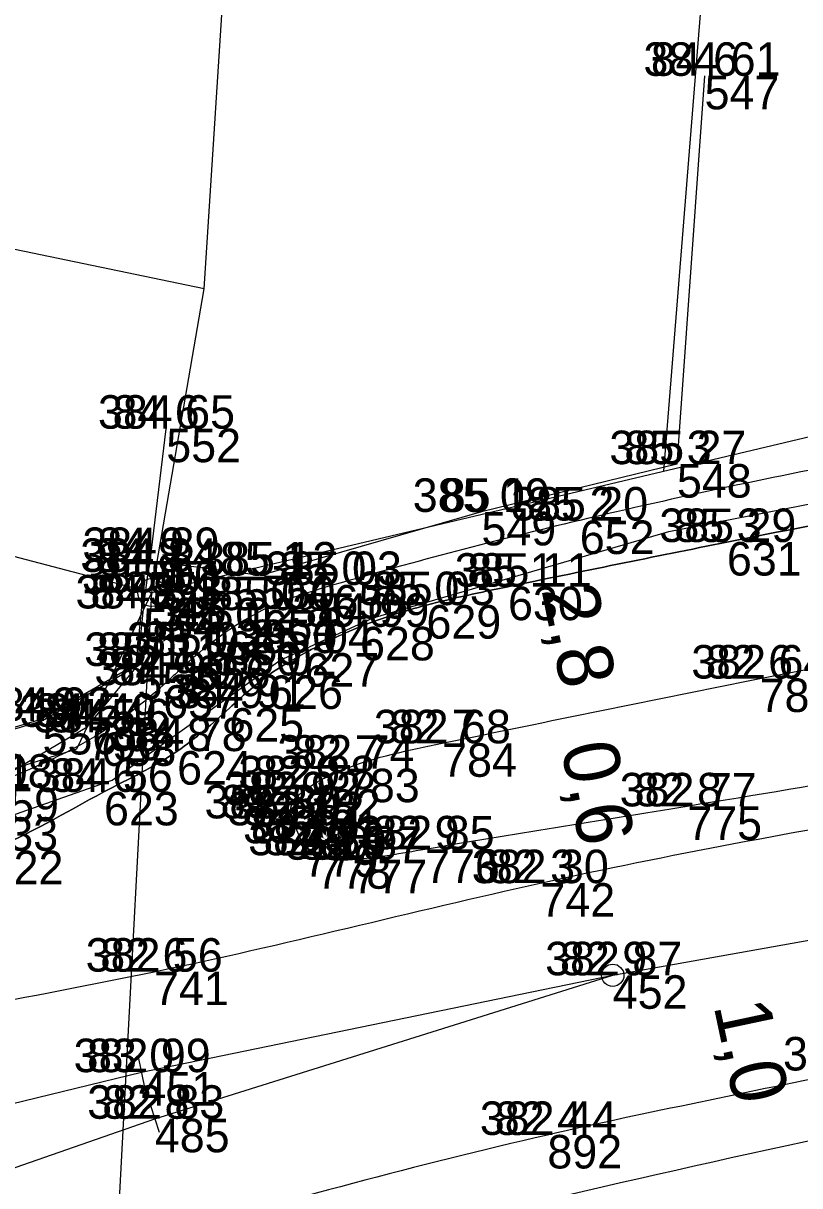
# Model space of a CAD drawing. Extents: x -514509 to -512782, y -1144610 to -1143439.
# Drawn here: x -513252.99 to -513225.18, y -1143600.5 to -1143558.86 of the extents above; entities that cross this region are included whole.
import ezdxf

# ---------------------------------------------------------------- set-up
doc = ezdxf.new("R2010")
doc.units = 0
for name, color, linetype in [('Vrstva 1', 7, 'Continuous'), ('Vrstva 10', 7, 'Continuous'), ('Vrstva 11', 7, 'Continuous'), ('Vrstva 12', 7, 'Continuous'), ('Vrstva 46', 7, 'Continuous'), ('Vrstva 48', 7, 'Continuous'), ('Vrstva 57', 7, 'Continuous'), ('Vrstva 58', 7, 'Continuous'), ('Vrstva 59', 7, 'Continuous'), ('Vrstva 6', 7, 'Continuous'), ('Vrstva 60', 7, 'Continuous'), ('Vrstva 8', 7, 'Continuous')]:
    doc.layers.add(name, color=color, linetype=linetype)

msp = doc.modelspace()

# ---------------------------------------------------------------- linework, layer by layer
at = {"layer": 'Vrstva 1'}
msp.add_lwpolyline([(-513255.856, -1143588.1), (-513249.812, -1143585.976), (-513243.787, -1143581.668), (-513240.465, -1143580.159), (-513229.874, -1143577.066), (-513220.491, -1143575.228), (-513193.623, -1143570.982)], dxfattribs=at)
at = {"layer": 'Vrstva 10'}
for p, q in [((-513250.415, -1143617.382), (-513248.39, -1143579.25)), ((-513248.442, -1143579.251), (-513248.342, -1143579.251)), ((-513248.442, -1143579.251), (-513248.342, -1143579.251)), ((-513248.442, -1143579.251), (-513248.342, -1143579.251)), ((-513248.442, -1143579.251), (-513248.342, -1143579.251)), ((-513248.401, -1143579.299), (-513248.379, -1143579.201)), ((-513248.401, -1143579.299), (-513248.379, -1143579.201)), ((-513248.401, -1143579.299), (-513248.379, -1143579.201))]:
    msp.add_line(p, q, dxfattribs=at)
for points in [[(-513582.696, -1143761.24), (-513581.966, -1143752.218), (-513543.007, -1143722.265), (-513536.98, -1143726.125), (-513503.11, -1143701.59), (-513467.163, -1143704.368), (-513409.406, -1143670.068), (-513367.763, -1143641.182), (-513337.875, -1143622.14), (-513302.677, -1143606.244), (-513297.569, -1143595.846), (-513289.461, -1143596.696), (-513287.694, -1143584.666), (-513262.147, -1143588.316), (-513251.067, -1143584.844), (-513248.39, -1143579.25), (-513218.784, -1143572.229), (-513191.434, -1143567.629), (-513154.1, -1143564.42), (-513082.649, -1143574.448)], [(-513582.696, -1143761.24), (-513581.966, -1143752.218), (-513543.007, -1143722.265), (-513536.98, -1143726.125), (-513503.11, -1143701.59), (-513467.163, -1143704.368), (-513409.406, -1143670.068), (-513367.763, -1143641.182), (-513337.875, -1143622.14), (-513302.677, -1143606.244), (-513297.569, -1143595.846), (-513289.461, -1143596.696), (-513287.694, -1143584.666), (-513262.147, -1143588.316), (-513251.067, -1143584.844), (-513248.39, -1143579.25), (-513218.784, -1143572.229), (-513191.434, -1143567.629), (-513154.1, -1143564.42), (-513082.649, -1143574.448)], [(-513248.898, -1143581.879), (-513252.304, -1143583.85), (-513256.484, -1143585.088), (-513261.272, -1143585.929), (-513266.919, -1143586.377), (-513271.818, -1143586.191), (-513275.455, -1143587.207), (-513272.851, -1143588.177), (-513269.418, -1143588.55)], [(-513254.387, -1143586.238), (-513250.697, -1143584.065), (-513248.898, -1143581.879)]]:
    msp.add_lwpolyline(points, dxfattribs=at)
for centre in [(-513248.392, -1143579.251), (-513248.392, -1143579.251), (-513248.392, -1143579.251), (-513248.392, -1143579.251), (-513248.39, -1143579.25), (-513248.39, -1143579.25), (-513248.39, -1143579.25)]:
    msp.add_circle(centre, 0.499, dxfattribs=at)
for points in [[(-513123.946, -1143569.095), (-513136.959, -1143567.384), (-513147.544, -1143566.738), (-513160.182, -1143566.568), (-513173.688, -1143567.587), (-513189.822, -1143569.464), (-513207.783, -1143571.88), (-513222.493, -1143574.402), (-513233.063, -1143576.666), (-513241.875, -1143578.979), (-513244.418, -1143579.885), (-513245.683, -1143580.636), (-513246.818, -1143581.512), (-513247.979, -1143582.57), (-513250.194, -1143584.261), (-513254.387, -1143586.238), (-513258.899, -1143587.657), (-513263.404, -1143588.363), (-513269.418, -1143588.55), (-513272.851, -1143588.177)], [(-513257.245, -1143589.431), (-513254.229, -1143588.505), (-513250.102, -1143586.392), (-513247.476, -1143584.933), (-513245.605, -1143583.389), (-513244.222, -1143582.217), (-513242.919, -1143581.425), (-513240.929, -1143580.476), (-513238.55, -1143579.701), (-513235.633, -1143579.04), (-513227.79, -1143577.445), (-513216.392, -1143575.319), (-513202.945, -1143573.374), (-513183.589, -1143570.866), (-513165.858, -1143569.141), (-513150.059, -1143568.836), (-513140.147, -1143569.606), (-513128.565, -1143571.075), (-513110.146, -1143573.354)], [(-513110.146, -1143573.354), (-513128.565, -1143571.075), (-513140.147, -1143569.606), (-513150.059, -1143568.836), (-513165.858, -1143569.141), (-513183.589, -1143570.866), (-513202.945, -1143573.374), (-513216.392, -1143575.319), (-513227.79, -1143577.445), (-513235.633, -1143579.04), (-513238.55, -1143579.701), (-513240.929, -1143580.476), (-513242.919, -1143581.425), (-513244.222, -1143582.217), (-513245.605, -1143583.389), (-513247.476, -1143584.933), (-513250.102, -1143586.392), (-513254.229, -1143588.505), (-513257.245, -1143589.431)], [(-513214.733, -1143584.448), (-513229.213, -1143586.91), (-513238.6, -1143588.453), (-513241.201, -1143588.819), (-513242.494, -1143588.658), (-513242.951, -1143588.231), (-513243.264, -1143587.589), (-513243.39, -1143586.875), (-513242.873, -1143586.302), (-513241.47, -1143585.565), (-513237.994, -1143584.65), (-513226.616, -1143582.332), (-513214.669, -1143580.21), (-513199.307, -1143578.201), (-513184.01, -1143576.618), (-513174.841, -1143576.254), (-513159.12, -1143575.498), (-513141.488, -1143576.138)], [(-513276.152, -1143596.997), (-513274.802, -1143597.59), (-513272.927, -1143598.05), (-513268.755, -1143597.873), (-513261.681, -1143595.809), (-513248.307, -1143592.834), (-513234.475, -1143589.658), (-513220.565, -1143587), (-513211.071, -1143585.455)], [(-513105.656, -1143589.572), (-513111.398, -1143588.825), (-513120.896, -1143588.124), (-513127.781, -1143587.815), (-513134.493, -1143587.399), (-513145.289, -1143587.917), (-513154.263, -1143588.165), (-513167.107, -1143589.025), (-513183.18, -1143590.33), (-513202.182, -1143592.368), (-513213.364, -1143594.183), (-513223.359, -1143596.374), (-513234.22, -1143598.682), (-513248.131, -1143602.316), (-513262.889, -1143606.569), (-513272.412, -1143609.783), (-513278.746, -1143612.526), (-513284.257, -1143615.463), (-513287.251, -1143617.25), (-513289.125, -1143618.716), (-513289.862, -1143619.586), (-513289.805, -1143620.367), (-513289.601, -1143620.971)], [(-513125.264, -1143589.045), (-513135.661, -1143588.368), (-513143.283, -1143588.407), (-513146.019, -1143588.597), (-513154.875, -1143589.536), (-513169.823, -1143590.946), (-513182.203, -1143592.15), (-513200.496, -1143594.572), (-513221.669, -1143598.242), (-513242.802, -1143603.101), (-513261.502, -1143608.166), (-513271.576, -1143611.724), (-513278.023, -1143614.872), (-513282.94, -1143617.541)]]:
    msp.add_spline(points, degree=3, dxfattribs=at)
at = {"layer": 'Vrstva 12'}
for points in [[(-513228.589, -1143560.737), (-513229.58, -1143574.652), (-513236.576, -1143576.364), (-513244.492, -1143578.643), (-513248.449, -1143578.123), (-513247.868, -1143573.38)], [(-513228.589, -1143560.737), (-513229.58, -1143574.652), (-513236.576, -1143576.364), (-513244.492, -1143578.643), (-513248.449, -1143578.123), (-513247.868, -1143573.38)], [(-513228.589, -1143560.737), (-513229.58, -1143574.652), (-513236.576, -1143576.364), (-513244.492, -1143578.643), (-513248.449, -1143578.123), (-513247.868, -1143573.38)], [(-513248.449, -1143578.123), (-513248.526, -1143578.514)], [(-513248.449, -1143578.123), (-513248.526, -1143578.514)], [(-513248.526, -1143578.514), (-513248.695, -1143579.822)], [(-513248.526, -1143578.514), (-513248.695, -1143579.822)], [(-513248.753, -1143579.775), (-513248.956, -1143581.832), (-513252.362, -1143583.803), (-513256.542, -1143585.041), (-513261.33, -1143585.882), (-513266.977, -1143586.33)], [(-513248.695, -1143579.822), (-513248.898, -1143581.879), (-513252.304, -1143583.85), (-513256.484, -1143585.088), (-513261.272, -1143585.929), (-513266.919, -1143586.377)], [(-513248.695, -1143579.822), (-513248.898, -1143581.879), (-513252.304, -1143583.85), (-513256.484, -1143585.088), (-513261.272, -1143585.929), (-513266.919, -1143586.377)]]:
    msp.add_lwpolyline(points, dxfattribs=at)
at = {"layer": 'Vrstva 46'}
for points in [[(-513228.589, -1143560.737), (-513229.58, -1143574.652), (-513236.576, -1143576.364), (-513244.492, -1143578.643), (-513248.449, -1143578.123), (-513247.868, -1143573.38)], [(-513248.449, -1143578.123), (-513248.526, -1143578.514)], [(-513248.526, -1143578.514), (-513248.695, -1143579.822)], [(-513248.695, -1143579.822), (-513248.898, -1143581.879), (-513252.304, -1143583.85), (-513256.484, -1143585.088), (-513261.272, -1143585.929), (-513266.919, -1143586.377)]]:
    msp.add_lwpolyline(points, dxfattribs=at)
at = {"layer": 'Vrstva 48'}
msp.add_line((-513248.442, -1143579.251), (-513248.342, -1143579.251), dxfattribs=at)
msp.add_circle((-513248.392, -1143579.251), 0.499, dxfattribs=at)
at = {"layer": 'Vrstva 6'}
for points in [[(-513413.969, -1143682.409), (-513403.805, -1143675.248), (-513392.133, -1143667.024), (-513380.381, -1143658.412), (-513367.637, -1143649.641), (-513357.691, -1143643.188), (-513346.467, -1143636.319), (-513334.512, -1143629.443), (-513322.183, -1143622.808), (-513313.555, -1143618.663), (-513300.91, -1143613.176), (-513292.314, -1143609.739), (-513280.019, -1143605.312), (-513267.676, -1143601.424), (-513256.27, -1143598.259), (-513248.762, -1143596.434), (-513231.877, -1143592.957), (-513218.03, -1143590.48), (-513208.28, -1143588.89)], [(-513473.254, -1143729.922), (-513459.481, -1143720.255), (-513446.15, -1143710.9), (-513437.145, -1143704.535), (-513426.35, -1143697.32), (-513415.342, -1143689.242), (-513413.529, -1143687.978), (-513401.76, -1143679.778), (-513389.139, -1143671.043), (-513376.721, -1143662.484), (-513364.496, -1143654.101), (-513352.892, -1143646.776), (-513340.089, -1143639.199), (-513329.801, -1143633.48), (-513318.088, -1143627.265), (-513306.168, -1143621.42), (-513292.483, -1143615.146), (-513278.194, -1143609.101), (-513263.261, -1143603.326), (-513248.282, -1143598.104), (-513231.877, -1143592.957)]]:
    msp.add_lwpolyline(points, dxfattribs=at)
at = {"layer": 'Vrstva 60'}
for p, q in [((-513228.59, -1143560.74), (-513228.59, -1143560.74)), ((-513247.87, -1143573.38), (-513247.87, -1143573.38)), ((-513229.58, -1143574.65), (-513229.58, -1143574.65)), ((-513236.58, -1143576.36), (-513236.58, -1143576.36)), ((-513233.06, -1143576.67), (-513233.06, -1143576.67)), ((-513227.79, -1143577.44), (-513227.79, -1143577.44)), ((-513248.45, -1143578.12), (-513248.45, -1143578.12)), ((-513248.53, -1143578.51), (-513248.53, -1143578.51)), ((-513244.49, -1143578.64), (-513244.49, -1143578.64)), ((-513241.88, -1143578.98), (-513241.88, -1143578.98)), ((-513235.63, -1143579.04), (-513235.63, -1143579.04)), ((-513248.39, -1143579.25), (-513248.39, -1143579.25)), ((-513248.7, -1143579.82), (-513248.7, -1143579.82)), ((-513244.42, -1143579.88), (-513244.42, -1143579.88)), ((-513238.55, -1143579.7), (-513238.55, -1143579.7)), ((-513245.68, -1143580.64), (-513245.68, -1143580.64)), ((-513240.93, -1143580.48), (-513240.93, -1143580.48)), ((-513246.82, -1143581.51), (-513246.82, -1143581.51)), ((-513242.92, -1143581.42), (-513242.92, -1143581.42)), ((-513248.9, -1143581.88), (-513248.9, -1143581.88)), ((-513244.22, -1143582.22), (-513244.22, -1143582.22)), ((-513226.62, -1143582.33), (-513226.62, -1143582.33)), ((-513247.98, -1143582.57), (-513247.98, -1143582.57)), ((-513245.61, -1143583.39), (-513245.61, -1143583.39)), ((-513252.3, -1143583.85), (-513252.3, -1143583.85)), ((-513250.7, -1143584.06), (-513250.7, -1143584.06)), ((-513250.19, -1143584.26), (-513250.19, -1143584.26)), ((-513237.99, -1143584.65), (-513237.99, -1143584.65)), ((-513247.48, -1143584.93), (-513247.48, -1143584.93)), ((-513241.47, -1143585.56), (-513241.47, -1143585.56)), ((-513250.1, -1143586.39), (-513250.1, -1143586.39)), ((-513242.87, -1143586.3), (-513242.87, -1143586.3)), ((-513243.39, -1143586.87), (-513243.39, -1143586.87)), ((-513229.21, -1143586.91), (-513229.21, -1143586.91)), ((-513244.04, -1143587.34), (-513244.04, -1143587.34)), ((-513243.26, -1143587.59), (-513243.26, -1143587.59)), ((-513242.95, -1143588.23), (-513242.95, -1143588.23)), ((-513238.6, -1143588.45), (-513238.6, -1143588.45)), ((-513242.49, -1143588.66), (-513242.49, -1143588.66)), ((-513241.2, -1143588.82), (-513241.2, -1143588.82)), ((-513234.47, -1143589.66), (-513234.47, -1143589.66)), ((-513248.31, -1143592.83), (-513248.31, -1143592.83)), ((-513231.88, -1143592.96), (-513231.88, -1143592.96)), ((-513248.76, -1143596.43), (-513248.76, -1143596.43)), ((-513248.28, -1143598.1), (-513248.28, -1143598.1)), ((-513234.22, -1143598.68), (-513234.22, -1143598.68))]:
    msp.add_line(p, q, dxfattribs=at)
at = {"layer": 'Vrstva 8'}
for p, q in [((-513225.43, -1143517.387), (-513230.062, -1143574.902)), ((-513248.863, -1143595.944), (-513248.66, -1143596.923)), ((-513248.434, -1143597.627), (-513248.129, -1143598.58))]:
    msp.add_line(p, q, dxfattribs=at)
for points in [[(-513248.39, -1143579.25), (-513246.509, -1143568.365), (-513245.688, -1143555.576), (-513244.124, -1143532.119), (-513243.762, -1143521.861), (-513243.25, -1143516.407), (-513242.174, -1143505.947), (-513250.332, -1143503.086), (-513258.171, -1143503.979), (-513270.878, -1143501.241)], [(-513246.509, -1143568.365), (-513266.87, -1143564.142), (-513267.555, -1143566.209), (-513265.928, -1143569.992), (-513266.625, -1143574.454)], [(-513285.741, -1143571.052), (-513277.74, -1143572.569), (-513275.312, -1143572.787), (-513272.999, -1143573.349), (-513266.625, -1143574.454), (-513248.39, -1143579.25)]]:
    msp.add_lwpolyline(points, dxfattribs=at)
msp.add_circle((-513231.88, -1143592.96), 0.4, dxfattribs=at)

# ---------------------------------------------------------------- texts
at = {"layer": 'Vrstva 11'}
for s, rotation, p in [('2,8', 281.5169, (-513234.438, -1143579.14)), ('0,6', 280.8194, (-513233.739, -1143584.77)), ('1,0', 281.9959, (-513228.272, -1143594.045))]:
    msp.add_text(s, height=2, rotation=rotation, dxfattribs=at).set_placement(p)
at = {"layer": 'Vrstva 57'}
for s, p in [('84 6 ', (-513230.514, -1143560.74)), ('84 6 ', (-513249.794, -1143573.38)), ('85 3 ', (-513231.463, -1143574.65)), ('85 1 ', (-513238.038, -1143576.36)), ('85 2 ', (-513234.943, -1143576.67)), ('85 3 ', (-513229.673, -1143577.44)), ('84 9 ', (-513250.338, -1143578.12)), ('84 8 ', (-513250.413, -1143578.51)), ('85 1 ', (-513245.948, -1143578.64)), ('85 0 ', (-513243.828, -1143578.98)), ('85 0 ', (-513250.338, -1143579.25)), ('85 1 ', (-513237.088, -1143579.04)), ('84 8 ', (-513250.583, -1143579.82)), ('85 0 ', (-513240.498, -1143579.7)), ('85 0 ', (-513246.368, -1143579.88)), ('85 0 ', (-513247.628, -1143580.64)), ('85 0 ', (-513242.878, -1143580.48)), ('85 0 ', (-513248.768, -1143581.51)), ('85 0 ', (-513244.868, -1143581.42)), ('85 1 ', (-513250.358, -1143581.88)), ('85 0 ', (-513246.168, -1143582.22)), ('82 6 ', (-513228.544, -1143582.33)), ('84 9 ', (-513249.868, -1143582.57)), ('84 9 ', (-513247.498, -1143583.39)), ('84 9 ', (-513254.188, -1143583.85)), ('84 5 ', (-513252.583, -1143584.06)), ('84 5 ', (-513252.073, -1143584.26)), ('82 7 ', (-513239.873, -1143584.65)), ('84 8 ', (-513249.363, -1143584.93)), ('82 7 ', (-513243.353, -1143585.56)), ('84 1 ', (-513255.848, -1143586.24)), ('84 6 ', (-513252.024, -1143586.39)), ('82 9 ', (-513244.758, -1143586.3)), ('82 9 ', (-513245.278, -1143586.87)), ('82 8 ', (-513231.093, -1143586.91)), ('83 8 ', (-513245.923, -1143587.34)), ('82 9 ', (-513245.148, -1143587.59)), ('82 9 ', (-513244.838, -1143588.23)), ('82 9 ', (-513240.488, -1143588.45)), ('82 9 ', (-513244.378, -1143588.66)), ('82 9 ', (-513243.088, -1143588.82)), ('82 3 ', (-513236.353, -1143589.66)), ('82 6 ', (-513250.234, -1143592.83)), ('82 9 ', (-513233.768, -1143592.96)), ('83 0 ', (-513250.708, -1143596.43)), ('82 8 ', (-513250.163, -1143598.1)), ('82 4 ', (-513236.103, -1143598.68))]:
    msp.add_text(s, height=1.2, dxfattribs=at).set_placement(p)
at = {"layer": 'Vrstva 58'}
for s, p in [('384 61', (-513230.78, -1143560.74)), ('384 65', (-513250.316, -1143573.38)), ('385 27', (-513232.001, -1143574.65)), ('385 09', (-513239.043, -1143576.36)), ('385 20', (-513235.52, -1143576.67)), ('385 29', (-513230.214, -1143577.44)), ('384 89', (-513250.874, -1143578.12)), ('384 84', (-513250.951, -1143578.51)), ('385 12', (-513246.656, -1143578.64)), ('385 03', (-513244.34, -1143578.98)), ('385 00', (-513250.888, -1143579.25)), ('385 11', (-513237.541, -1143579.04)), ('384 84', (-513251.121, -1143579.82)), ('385 03', (-513241.01, -1143579.7)), ('385 04', (-513246.88, -1143579.88)), ('385 02', (-513248.14, -1143580.64)), ('384 99', (-513243.358, -1143580.48)), ('385 02', (-513249.28, -1143581.51)), ('385 04', (-513245.38, -1143581.42)), ('385 11', (-513250.811, -1143581.88)), ('385 02', (-513246.68, -1143582.22)), ('382 64', (-513229.066, -1143582.33)), ('384 90', (-513250.443, -1143582.57)), ('384 91', (-513247.78, -1143583.39)), ('384 92', (-513254.724, -1143583.85)), ('384 49', (-513253.124, -1143584.06)), ('384 46', (-513252.636, -1143584.26)), ('382 68', (-513240.436, -1143584.65)), ('384 78', (-513249.901, -1143584.93)), ('382 74', (-513243.891, -1143585.56)), ('384 08', (-513256.85, -1143586.24)), ('384 56', (-513252.546, -1143586.39)), ('382 88', (-513245.291, -1143586.3)), ('382 92', (-513245.814, -1143586.87)), ('382 77', (-513231.631, -1143586.91)), ('383 80', (-513246.5, -1143587.34)), ('382 92', (-513245.684, -1143587.59)), ('384 33', (-513256.651, -1143588.5)), ('382 91', (-513245.12, -1143588.23)), ('382 85', (-513241.021, -1143588.45)), ('382 86', (-513244.936, -1143588.66)), ('382 87', (-513243.621, -1143588.82)), ('382 30', (-513236.93, -1143589.66)), ('382 56', (-513250.756, -1143592.83)), ('382 87', (-513234.301, -1143592.96)), ('382 99', (-513251.188, -1143596.43)), ('382 35', (-513225.781, -1143596.37)), ('382 83', (-513250.701, -1143598.1)), ('382 44', (-513236.641, -1143598.68))]:
    msp.add_text(s, height=1.2, dxfattribs=at).set_placement(p)
at = {"layer": 'Vrstva 59'}
for s, p in [('547', (-513228.59, -1143561.94)), ('552', (-513247.87, -1143574.58)), ('548', (-513229.58, -1143575.85)), ('549', (-513236.58, -1143577.56)), ('652', (-513233.06, -1143577.87)), ('631', (-513227.79, -1143578.64)), ('551', (-513248.45, -1143579.32)), ('553', (-513248.53, -1143579.71)), ('550', (-513244.49, -1143579.84)), ('653', (-513241.88, -1143580.18)), ('630', (-513235.63, -1143580.24)), ('545', (-513248.39, -1143580.45)), ('554', (-513248.7, -1143581.02)), ('654', (-513244.42, -1143581.08)), ('629', (-513238.55, -1143580.9)), ('655', (-513245.68, -1143581.84)), ('628', (-513240.93, -1143581.68)), ('656', (-513246.82, -1143582.71)), ('627', (-513242.92, -1143582.62)), ('555', (-513248.9, -1143583.08)), ('626', (-513244.22, -1143583.42)), ('785', (-513226.62, -1143583.53)), ('657', (-513247.98, -1143583.77)), ('625', (-513245.61, -1143584.59)), ('556', (-513252.3, -1143585.05)), ('796', (-513250.7, -1143585.26)), ('658', (-513250.19, -1143585.46)), ('784', (-513237.99, -1143585.85)), ('624', (-513247.48, -1143586.13)), ('783', (-513241.47, -1143586.76)), ('659', (-513254.39, -1143587.44)), ('623', (-513250.1, -1143587.59)), ('782', (-513242.87, -1143587.5)), ('781', (-513243.39, -1143588.07)), ('775', (-513229.21, -1143588.11)), ('705', (-513244.04, -1143588.54)), ('780', (-513243.26, -1143588.79)), ('779', (-513242.95, -1143589.43)), ('622', (-513254.23, -1143589.7)), ('776', (-513238.6, -1143589.65)), ('778', (-513242.49, -1143589.86)), ('777', (-513241.2, -1143590.02)), ('742', (-513234.47, -1143590.86)), ('741', (-513248.31, -1143594.03)), ('452', (-513231.88, -1143594.16)), ('451', (-513248.76, -1143597.63)), ('485', (-513248.28, -1143599.3)), ('892', (-513234.22, -1143599.88))]:
    msp.add_text(s, height=1.2, dxfattribs=at).set_placement(p)

doc.saveas('drawing.dxf')
